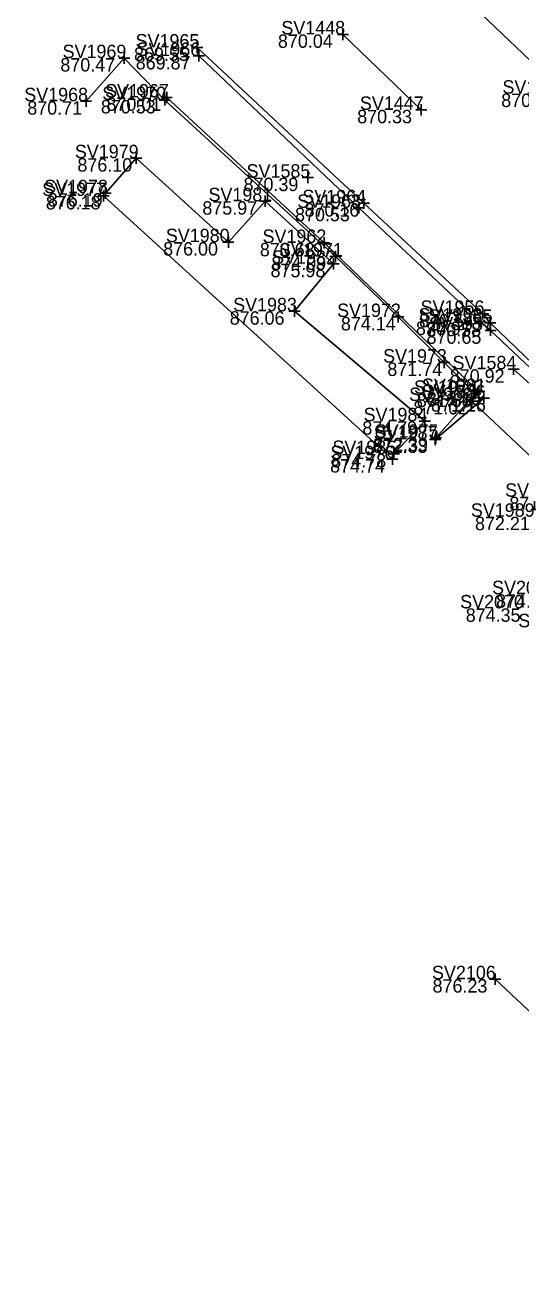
# Model space of a CAD drawing. Extents: x 1480001 to 1480402, y 379235 to 379603.
# Drawn here: x 1480000.6 to 1480045, y 379434.1 to 379546.7 of the extents above; entities that cross this region are included whole.
import ezdxf

# ---------------------------------------------------------------- set-up
doc = ezdxf.new("R2010")
doc.units = 0
for name, color, linetype in [('BD_X_Building', 7, 'Continuous'), ('PM_P_CL_Double_Solid', 7, 'Continuous'), ('PM_X_Lane_Line', 7, 'Continuous'), ('PV_X_Curb', 7, 'Continuous'), ('PV_X_Driveway', 7, 'Continuous'), ('PV_X_Steps', 7, 'Continuous'), ('PV_X_Walk', 7, 'Continuous'), ('RD_X_Concrete_Pad', 7, 'Continuous'), ('SV_X_Shot_Marker', 7, 'Continuous'), ('SV_X_Text_Elevation', 7, 'Continuous'), ('SV_X_Text_Name', 7, 'Continuous'), ('UT_X_Water', 7, 'Continuous')]:
    doc.layers.add(name, color=color, linetype=linetype)

msp = doc.modelspace()

# ---------------------------------------------------------------- linework, layer by layer
at = {"layer": 'BD_X_Building'}
for p, q in [((1480033.54, 379507.83), (1480007.66, 379531.38)), ((1480070.12, 379435.6), (1480042.74, 379461.28))]:
    msp.add_line(p, q, dxfattribs=at)
at = {"layer": 'PM_P_CL_Double_Solid'}
msp.add_lwpolyline([(1480030.31, 379558.37), (1480048.99, 379540.54), (1480068.18, 379522.46), (1480086.7, 379505.16), (1480104.25, 379488.61), (1480122.28, 379471.9), (1480139.96, 379455.6)], dxfattribs=at)
at = {"layer": 'PM_X_Lane_Line'}
msp.add_line((1480036.13, 379539.09), (1480029.11, 379545.84), dxfattribs=at)
at = {"layer": 'PV_X_Curb'}
for points in [[(1480135.19, 379432.33), (1480118.45, 379448.16), (1480110.15, 379455.95), (1480109.27, 379456.61), (1480100.92, 379464.72), (1480096.04, 379469.27), (1480093.78, 379471.44), (1480091.42, 379473.76), (1480089.15, 379475.88), (1480069.41, 379494.5), (1480056.46, 379506.38), (1480055.44, 379507.42), (1480042.3, 379520.02), (1480041.64, 379520.83), (1480030.98, 379530.73), (1480016.06, 379544.67)], [(1480135, 379431.9), (1480118.04, 379447.91), (1480109.91, 379455.65), (1480108.98, 379456.44), (1480100.47, 379464.44), (1480095.65, 379469.16), (1480093.39, 379471.31), (1480093.13, 379470.94), (1480088.62, 379475.04), (1480088.84, 379475.37), (1480068.91, 379494.28), (1480056.26, 379506.21), (1480055.2, 379507.24), (1480042.34, 379519.35), (1480041.39, 379520.14), (1480030.54, 379530.32), (1480016.21, 379543.91)]]:
    msp.add_lwpolyline(points, dxfattribs=at)
at = {"layer": 'PV_X_Driveway'}
msp.add_line((1480041.73, 379513.28), (1480037.37, 379509.59), dxfattribs=at)
at = {"layer": 'PV_X_Steps'}
msp.add_lwpolyline([(1480006.1, 379539.86), (1480009.53, 379543.72), (1480013.15, 379539.97), (1480028.44, 379525.96), (1480034.06, 379520.55), (1480038.19, 379516.47), (1480040.95, 379513.68), (1480037.44, 379509.74)], dxfattribs=at)
at = {"layer": 'PV_X_Walk'}
msp.add_lwpolyline([(1480132.9, 379425.97), (1480114.83, 379442.96), (1480103.25, 379453.81), (1480091.01, 379465.63), (1480083.55, 379472.51), (1480065.12, 379489.82), (1480051.08, 379503.11), (1480050.67, 379503.61), (1480040.66, 379513.03), (1480041.27, 379513.84), (1480027.42, 379527.18), (1480013.33, 379540.2)], dxfattribs=at)
at = {"layer": 'RD_X_Concrete_Pad'}
msp.add_lwpolyline([(1480007.84, 379531.63), (1480010.59, 379534.76), (1480018.85, 379527.25), (1480022.14, 379530.91), (1480028.26, 379525.31), (1480024.78, 379521.06), (1480036.45, 379511.22), (1480033.67, 379508.29)], dxfattribs=at)
at = {"layer": 'SV_X_Shot_Marker'}
for p, q in [((1480029.11, 379546.34), (1480029.11, 379545.34)), ((1480016.06, 379545.17), (1480016.06, 379544.17)), ((1480028.61, 379545.84), (1480029.61, 379545.84)), ((1480029.11, 379545.84), (1480029.11, 379545.84)), ((1480009.53, 379544.22), (1480009.53, 379543.22)), ((1480015.56, 379544.67), (1480016.56, 379544.67)), ((1480016.06, 379544.67), (1480016.06, 379544.67)), ((1480016.21, 379544.41), (1480016.21, 379543.41)), ((1480009.03, 379543.72), (1480010.03, 379543.72)), ((1480009.53, 379543.72), (1480009.53, 379543.72)), ((1480015.71, 379543.91), (1480016.71, 379543.91)), ((1480016.21, 379543.91), (1480016.21, 379543.91)), ((1480013.33, 379540.7), (1480013.33, 379539.7)), ((1480005.6, 379539.86), (1480006.6, 379539.86)), ((1480006.1, 379540.36), (1480006.1, 379539.36)), ((1480006.1, 379539.86), (1480006.1, 379539.86)), ((1480012.65, 379539.97), (1480013.65, 379539.97)), ((1480012.83, 379540.2), (1480013.83, 379540.2)), ((1480013.15, 379540.47), (1480013.15, 379539.47)), ((1480013.15, 379539.97), (1480013.15, 379539.97)), ((1480013.33, 379540.2), (1480013.33, 379540.2)), ((1480036.13, 379539.59), (1480036.13, 379538.59)), ((1480035.63, 379539.09), (1480036.63, 379539.09)), ((1480036.13, 379539.09), (1480036.13, 379539.09)), ((1480010.59, 379535.26), (1480010.59, 379534.26)), ((1480010.09, 379534.76), (1480011.09, 379534.76)), ((1480010.59, 379534.76), (1480010.59, 379534.76)), ((1480025.46, 379533.02), (1480026.46, 379533.02)), ((1480025.96, 379533.52), (1480025.96, 379532.52)), ((1480025.96, 379533.02), (1480025.96, 379533.02)), ((1480007.34, 379531.63), (1480008.34, 379531.63)), ((1480007.66, 379531.88), (1480007.66, 379530.88)), ((1480007.84, 379532.13), (1480007.84, 379531.13)), ((1480007.84, 379531.63), (1480007.84, 379531.63)), ((1480007.16, 379531.38), (1480008.16, 379531.38)), ((1480007.66, 379531.38), (1480007.66, 379531.38)), ((1480021.64, 379530.91), (1480022.64, 379530.91)), ((1480022.14, 379531.41), (1480022.14, 379530.41)), ((1480022.14, 379530.91), (1480022.14, 379530.91)), ((1480030.48, 379530.73), (1480031.48, 379530.73)), ((1480030.54, 379530.82), (1480030.54, 379529.82)), ((1480030.98, 379531.23), (1480030.98, 379530.23)), ((1480030.98, 379530.73), (1480030.98, 379530.73)), ((1480030.04, 379530.32), (1480031.04, 379530.32)), ((1480030.54, 379530.32), (1480030.54, 379530.32)), ((1480018.35, 379527.25), (1480019.35, 379527.25)), ((1480018.85, 379527.75), (1480018.85, 379526.75)), ((1480018.85, 379527.25), (1480018.85, 379527.25)), ((1480026.92, 379527.18), (1480027.92, 379527.18)), ((1480027.42, 379527.68), (1480027.42, 379526.68)), ((1480027.42, 379527.18), (1480027.42, 379527.18)), ((1480028.44, 379526.46), (1480028.44, 379525.46)), ((1480027.76, 379525.31), (1480028.76, 379525.31)), ((1480027.94, 379525.96), (1480028.94, 379525.96)), ((1480028.26, 379525.81), (1480028.26, 379524.81)), ((1480028.26, 379525.31), (1480028.26, 379525.31)), ((1480028.44, 379525.96), (1480028.44, 379525.96)), ((1480024.78, 379521.56), (1480024.78, 379520.56)), ((1480024.28, 379521.06), (1480025.28, 379521.06)), ((1480024.78, 379521.06), (1480024.78, 379521.06)), ((1480033.56, 379520.55), (1480034.56, 379520.55)), ((1480034.06, 379521.05), (1480034.06, 379520.05)), ((1480034.06, 379520.55), (1480034.06, 379520.55)), ((1480041.14, 379520.83), (1480042.14, 379520.83)), ((1480041.39, 379520.64), (1480041.39, 379519.64)), ((1480041.64, 379521.33), (1480041.64, 379520.33)), ((1480041.64, 379520.83), (1480041.64, 379520.83)), ((1480042.3, 379520.52), (1480042.3, 379519.52)), ((1480040.89, 379520.14), (1480041.89, 379520.14)), ((1480041.39, 379520.14), (1480041.39, 379520.14)), ((1480041.8, 379520.02), (1480042.8, 379520.02)), ((1480041.84, 379519.35), (1480042.84, 379519.35)), ((1480042.3, 379520.02), (1480042.3, 379520.02)), ((1480042.34, 379519.85), (1480042.34, 379518.85)), ((1480042.34, 379519.35), (1480042.34, 379519.35)), ((1480038.19, 379516.97), (1480038.19, 379515.97)), ((1480037.69, 379516.47), (1480038.69, 379516.47)), ((1480038.19, 379516.47), (1480038.19, 379516.47)), ((1480043.9, 379515.87), (1480044.9, 379515.87)), ((1480044.4, 379516.37), (1480044.4, 379515.37)), ((1480044.4, 379515.87), (1480044.4, 379515.87)), ((1480040.45, 379513.68), (1480041.45, 379513.68)), ((1480040.77, 379513.84), (1480041.77, 379513.84)), ((1480040.95, 379514.18), (1480040.95, 379513.18)), ((1480040.95, 379513.68), (1480040.95, 379513.68)), ((1480041.27, 379514.34), (1480041.27, 379513.34)), ((1480041.27, 379513.84), (1480041.27, 379513.84)), ((1480041.73, 379513.78), (1480041.73, 379512.78)), ((1480040.16, 379513.03), (1480041.16, 379513.03)), ((1480040.66, 379513.53), (1480040.66, 379512.53)), ((1480040.66, 379513.03), (1480040.66, 379513.03)), ((1480041.23, 379513.28), (1480042.23, 379513.28)), ((1480041.73, 379513.28), (1480041.73, 379513.28)), ((1480036.45, 379511.72), (1480036.45, 379510.72)), ((1480035.95, 379511.22), (1480036.95, 379511.22)), ((1480036.45, 379511.22), (1480036.45, 379511.22)), ((1480037.44, 379510.24), (1480037.44, 379509.24)), ((1480036.87, 379509.59), (1480037.87, 379509.59)), ((1480036.94, 379509.74), (1480037.94, 379509.74)), ((1480037.37, 379510.09), (1480037.37, 379509.09)), ((1480037.37, 379509.59), (1480037.37, 379509.59)), ((1480037.44, 379509.74), (1480037.44, 379509.74)), ((1480033.17, 379508.29), (1480034.17, 379508.29)), ((1480033.54, 379508.33), (1480033.54, 379507.33)), ((1480033.67, 379508.79), (1480033.67, 379507.79)), ((1480033.67, 379508.29), (1480033.67, 379508.29)), ((1480033.04, 379507.83), (1480034.04, 379507.83)), ((1480033.54, 379507.83), (1480033.54, 379507.83)), ((1480042.24, 379461.28), (1480043.24, 379461.28)), ((1480042.74, 379461.78), (1480042.74, 379460.78)), ((1480042.74, 379461.28), (1480042.74, 379461.28))]:
    msp.add_line(p, q, dxfattribs=at)
at = {"layer": 'UT_X_Water'}
msp.add_lwpolyline([(1480225.09, 379345.6), (1480208.32, 379361.34), (1480207.35, 379362.25), (1480199.53, 379369.77), (1480193.21, 379375.65), (1480182.82, 379385.14), (1480177.93, 379389.52), (1480169.42, 379398.32), (1480161.04, 379406.19), (1480144.92, 379421.02), (1480134.74, 379430.56), (1480121.49, 379442), (1480113.09, 379450.37), (1480106.42, 379456.91), (1480094.54, 379467.99), (1480089.15, 379472.55), (1480086.75, 379474.71), (1480073.46, 379487.34), (1480068.12, 379493.19), (1480050.68, 379510.21), (1480044.4, 379515.87)], dxfattribs=at)

# ---------------------------------------------------------------- texts
at = {"layer": 'SV_X_Text_Elevation'}
for s, p in [('870.04', (1480023.29, 379544.64)), ('869.55', (1480010.4, 379543.47)), ('870.47', (1480003.8, 379542.52)), ('869.87', (1480010.55, 379542.71)), ('870.71', (1480000.84, 379538.66)), ('870.53', (1480007.43, 379538.77)), ('870.01', (1480007.93, 379539)), ('870.78', (1480043.29, 379539.34)), ('870.33', (1480030.39, 379537.89)), ('876.10', (1480005.33, 379533.56)), ('870.39', (1480020.21, 379531.82)), ('876.19', (1480002.68, 379530.43)), ('876.18', (1480002.5, 379530.18)), ('875.97', (1480016.52, 379529.71)), ('870.16', (1480025.67, 379529.53)), ('870.53', (1480024.82, 379529.12)), ('876.00', (1480013.01, 379526.05)), ('870.68', (1480021.67, 379525.98)), ('874.09', (1480022.7, 379524.76)), ('875.98', (1480022.63, 379524.11)), ('876.06', (1480018.97, 379519.86)), ('874.14', (1480028.93, 379519.35)), ('870.54', (1480035.93, 379519.63)), ('870.97', (1480035.65, 379518.94)), ('870.58', (1480036.58, 379518.82)), ('870.65', (1480036.6, 379518.15)), ('871.74', (1480033.09, 379515.27)), ('870.92', (1480038.68, 379514.67)), ('871.66', (1480035.72, 379512.48)), ('871.15', (1480036.62, 379512.64)), ('871.02', (1480035.42, 379511.83)), ('871.16', (1480037, 379512.08)), ('874.79', (1480030.85, 379510.02)), ('872.33', (1480031.77, 379508.39)), ('872.39', (1480031.82, 379508.54)), ('874.78', (1480028.07, 379507.09)), ('874.74', (1480027.96, 379506.63)), ('871.52', (1480044.02, 379503.26)), ('872.21', (1480040.94, 379501.47)), ('874.04', (1480042.83, 379494.54)), ('874.35', (1480040.11, 379493.27)), ('876.23', (1480037.14, 379460.08))]:
    msp.add_text(s, height=1.2, dxfattribs=at).set_placement(p)
at = {"layer": 'SV_X_Text_Name'}
for s, p in [('SV1448', (1480023.6, 379545.84)), ('SV1965', (1480010.54, 379544.67)), ('SV1966', (1480010.62, 379543.91)), ('SV1969', (1480004, 379543.72)), ('SV1450', (1480043.4, 379540.54)), ('SV1968', (1480000.57, 379539.86)), ('SV1970', (1480007.56, 379539.97)), ('SV1967', (1480007.81, 379540.2)), ('SV1447', (1480030.63, 379539.09)), ('SV1979', (1480005.1, 379534.76)), ('SV1585', (1480020.48, 379533.02)), ('SV1978', (1480002.35, 379531.63)), ('SV1977', (1480002.18, 379531.38)), ('SV1981', (1480017.07, 379530.91)), ('SV1964', (1480025.48, 379530.73)), ('SV1963', (1480025.02, 379530.32)), ('SV1980', (1480013.25, 379527.25)), ('SV1962', (1480021.91, 379527.18)), ('SV1971', (1480023.39, 379525.96)), ('SV1982', (1480022.77, 379525.31)), ('SV1983', (1480019.28, 379521.06)), ('SV1972', (1480028.59, 379520.55)), ('SV1956', (1480036.07, 379520.83)), ('SV1958', (1480035.88, 379520.14)), ('SV1955', (1480036.8, 379520.02)), ('SV1957', (1480036.84, 379519.35)), ('SV1973', (1480032.71, 379516.47)), ('SV1584', (1480038.93, 379515.87)), ('SV1974', (1480035.48, 379513.68)), ('SV1961', (1480036.19, 379513.84)), ('SV1960', (1480035.04, 379513.03)), ('SV1986', (1480036.16, 379513.28)), ('SV1984', (1480030.96, 379511.22)), ('SV1987', (1480031.87, 379509.59)), ('SV1975', (1480031.96, 379509.74)), ('SV1985', (1480028.17, 379508.29)), ('SV1976', (1480027.99, 379507.83)), ('SV1988', (1480043.64, 379504.46)), ('SV1989', (1480040.57, 379502.67)), ('SV2069', (1480042.47, 379495.74)), ('SV2070', (1480039.61, 379494.47)), ('SV2068', (1480044.82, 379492.78)), ('SV2106', (1480037.09, 379461.28))]:
    msp.add_text(s, height=1.2, dxfattribs=at).set_placement(p)

doc.saveas('drawing.dxf')
